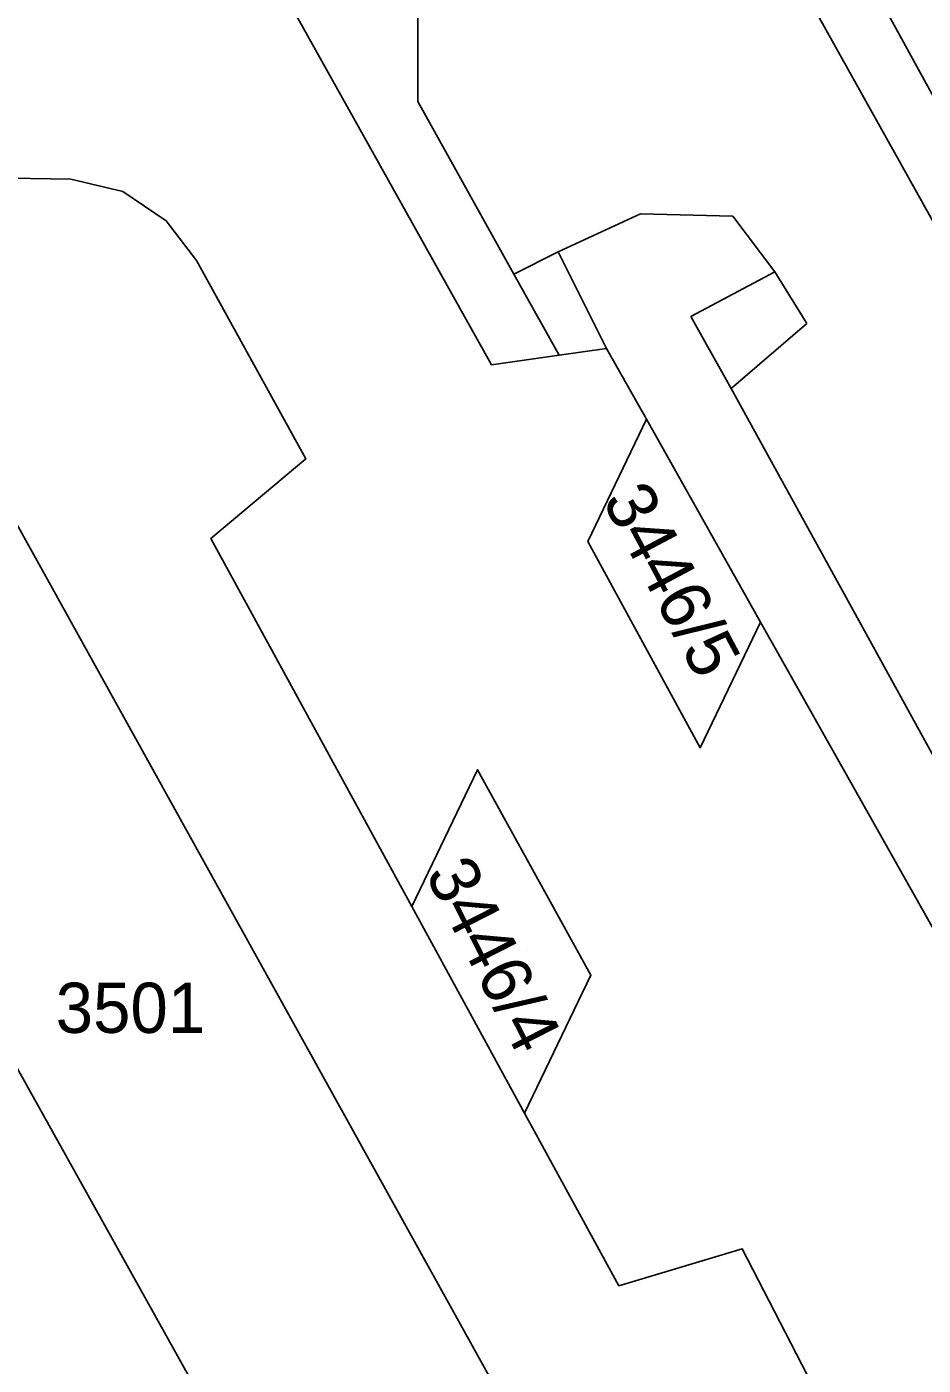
# Model space of a CAD drawing. Extents: x -262715 to -259381, y -1237238 to -1231182.
# Drawn here: x -261417 to -261381.4, y -1235699.9 to -1235646.6 of the extents above; entities that cross this region are included whole.
import ezdxf

# ---------------------------------------------------------------- set-up
doc = ezdxf.new("R2010")
doc.units = 0
for name, color, linetype in [('body_kn', 7, 'Continuous'), ('kladpar_druhypozemkov', 7, 'Continuous'), ('kladpar_hranice', 7, 'Continuous'), ('kladpar_parcelnecisla', 7, 'Continuous'), ('kladpar_plochy', 7, 'Continuous'), ('zappar_hrandruhpozemk', 7, 'Continuous')]:
    doc.layers.add(name, color=color, linetype=linetype)

msp = doc.modelspace()

# ---------------------------------------------------------------- linework, layer by layer
at = {"layer": 'body_kn'}
for p, q in [((-261401.47, -1235649.56), (-261401.47, -1235649.56)), ((-261415.28, -1235652.66), (-261415.28, -1235652.66)), ((-261413.21, -1235653.15), (-261413.21, -1235653.15)), ((-261392.61, -1235654.03), (-261392.61, -1235654.03)), ((-261388.94, -1235654.12), (-261388.94, -1235654.12)), ((-261411.48, -1235654.31), (-261411.48, -1235654.31)), ((-261410.28, -1235655.89), (-261410.28, -1235655.89)), ((-261395.88, -1235655.54), (-261395.88, -1235655.54)), ((-261395.88, -1235655.54), (-261395.88, -1235655.54)), ((-261387.26, -1235656.34), (-261387.26, -1235656.34)), ((-261397.65, -1235656.43), (-261397.65, -1235656.43)), ((-261397.65, -1235656.43), (-261397.65, -1235656.43)), ((-261390.6, -1235658.12), (-261390.6, -1235658.12)), ((-261385.99, -1235658.4), (-261385.99, -1235658.4)), ((-261393.96, -1235659.39), (-261393.96, -1235659.39)), ((-261398.54, -1235660.04), (-261398.54, -1235660.04)), ((-261395.85, -1235659.66), (-261395.85, -1235659.66)), ((-261389, -1235660.98), (-261389, -1235660.98)), ((-261389, -1235660.98), (-261389, -1235660.98)), ((-261392.37, -1235662.21), (-261392.37, -1235662.21)), ((-261392.37, -1235662.21), (-261392.37, -1235662.21)), ((-261405.93, -1235663.79), (-261405.93, -1235663.79)), ((-261405.93, -1235663.79), (-261405.93, -1235663.79)), ((-261409.71, -1235666.96), (-261409.71, -1235666.96)), ((-261394.71, -1235667.07), (-261394.71, -1235667.07)), ((-261387.83, -1235670.28), (-261387.83, -1235670.28)), ((-261387.83, -1235670.28), (-261387.83, -1235670.28)), ((-261390.23, -1235675.28), (-261390.23, -1235675.28)), ((-261399.09, -1235676.16), (-261399.09, -1235676.16)), ((-261401.71, -1235681.6), (-261401.71, -1235681.6)), ((-261401.71, -1235681.6), (-261401.71, -1235681.6)), ((-261394.58, -1235684.33), (-261394.58, -1235684.33)), ((-261397.22, -1235689.82), (-261397.22, -1235689.82)), ((-261397.22, -1235689.82), (-261397.22, -1235689.82)), ((-261388.56, -1235695.22), (-261388.56, -1235695.22)), ((-261393.47, -1235696.69), (-261393.47, -1235696.69))]:
    msp.add_line(p, q, dxfattribs=at)
at = {"layer": 'kladpar_druhypozemkov'}
for p, q in [((-261389.98, -1235668.92), (-261389.98, -1235668.92)), ((-261397.12, -1235683.38), (-261397.12, -1235683.38)), ((-261413.17, -1235684.66), (-261413.17, -1235684.66))]:
    msp.add_line(p, q, dxfattribs=at)
at = {"layer": 'kladpar_hranice'}
for p, q in [((-261392.37, -1235662.21), (-261387.83, -1235670.28)), ((-261397.22, -1235689.82), (-261401.71, -1235681.6))]:
    msp.add_line(p, q, dxfattribs=at)
for points in [[(-261589.5, -1235316.23), (-261558.55, -1235373.38), (-261545.48, -1235395.38), (-261529.32, -1235425.1), (-261511.21, -1235458.13), (-261492.65, -1235492.14), (-261486.88, -1235501.6), (-261475.01, -1235519.76), (-261455.64, -1235559.31), (-261446.9, -1235569.53), (-261445.58, -1235571), (-261434.14, -1235591.59), (-261432.99, -1235593.76), (-261426.79, -1235608.76), (-261415.88, -1235628.94), (-261409.46, -1235640.49), (-261398.54, -1235660.04), (-261395.85, -1235659.66), (-261393.96, -1235659.39), (-261392.37, -1235662.21)], [(-261401.71, -1235681.6), (-261409.71, -1235666.96), (-261405.93, -1235663.79), (-261410.28, -1235655.89), (-261411.48, -1235654.31), (-261413.21, -1235653.15), (-261415.28, -1235652.66), (-261418.53, -1235652.6), (-261420.69, -1235653.54), (-261424.38, -1235647.44), (-261421.97, -1235645.54), (-261420.75, -1235643.18), (-261420.2, -1235640.22), (-261420.71, -1235637.44), (-261425.09, -1235629.28), (-261435.51, -1235617.79), (-261446.22, -1235598.57), (-261448.98, -1235591.27), (-261453.34, -1235581.02), (-261459.9, -1235567.4), (-261464.77, -1235569.24), (-261486.46, -1235529.8), (-261505.16, -1235495.58)], [(-261390.22, -1235736.84), (-261437.66, -1235651.7), (-261461.76, -1235608.43), (-261467.86, -1235597.89), (-261523.57, -1235497.42)], [(-261352.7, -1235701.57), (-261356.45, -1235698.78), (-261375.96, -1235663.31), (-261392.09, -1235634.4), (-261401.48, -1235640.18), (-261403.28, -1235637.04), (-261396.15, -1235632.64), (-261395.33, -1235631.71), (-261395.49, -1235630.29), (-261406.15, -1235610.79), (-261420.15, -1235585.99), (-261421.33, -1235584.92), (-261422.94, -1235585.32), (-261434.14, -1235591.59), (-261445.58, -1235571), (-261446.9, -1235569.53), (-261442.73, -1235566.89), (-261441.26, -1235564.87), (-261441.82, -1235562.85), (-261455.34, -1235538.18), (-261469.51, -1235511.93), (-261466.57, -1235510.22)], [(-261368.01, -1235705.48), (-261387.83, -1235670.28), (-261392.37, -1235662.21), (-261393.96, -1235659.39), (-261395.85, -1235659.66), (-261398.54, -1235660.04), (-261409.46, -1235640.49), (-261415.88, -1235628.94), (-261426.79, -1235608.76), (-261432.99, -1235593.76), (-261434.14, -1235591.59), (-261422.94, -1235585.32), (-261421.33, -1235584.92), (-261420.15, -1235585.99), (-261406.15, -1235610.79), (-261395.49, -1235630.29), (-261395.33, -1235631.71), (-261396.15, -1235632.64), (-261403.28, -1235637.04)], [(-261407.7, -1235600.94), (-261403.03, -1235609.1), (-261401.85, -1235611.11), (-261394.91, -1235623.98), (-261393.78, -1235625.97), (-261388.88, -1235634.8), (-261387.77, -1235636.94), (-261380.64, -1235649.93), (-261379.45, -1235652.11), (-261375.1, -1235660.07), (-261373.94, -1235662.27), (-261366.9, -1235675.1), (-261365.77, -1235677.17), (-261354.62, -1235697.41), (-261352.48, -1235699.44), (-261349.4, -1235698.97), (-261332.6, -1235689.38)], [(-261332.6, -1235689.38), (-261349.4, -1235698.97), (-261352.48, -1235699.44), (-261354.62, -1235697.41), (-261365.77, -1235677.17), (-261366.9, -1235675.1), (-261373.94, -1235662.27), (-261375.1, -1235660.07), (-261379.45, -1235652.11), (-261380.64, -1235649.93), (-261387.77, -1235636.94), (-261388.88, -1235634.8), (-261393.78, -1235625.97), (-261394.91, -1235623.98), (-261401.85, -1235611.11), (-261403.03, -1235609.1), (-261407.7, -1235600.94)], [(-261452.54, -1235603.16), (-261442.43, -1235621.28), (-261431.37, -1235641.24), (-261434.67, -1235644.77), (-261433.26, -1235646.14), (-261431.36, -1235647.27), (-261429.38, -1235647.89), (-261427.07, -1235648.14), (-261424.38, -1235647.44), (-261420.69, -1235653.54), (-261422.8, -1235655.3), (-261424.28, -1235657.92), (-261424.54, -1235661.82), (-261423.27, -1235664.95), (-261418.92, -1235663.7), (-261397.54, -1235702.26)], [(-261488.56, -1235619.47), (-261468.61, -1235607.37), (-261467.06, -1235606.61), (-261465.15, -1235606.35), (-261463.23, -1235606.99), (-261461.76, -1235608.43), (-261437.66, -1235651.7), (-261390.22, -1235736.84)], [(-261365.39, -1235703.9), (-261389, -1235660.98), (-261390.6, -1235658.12), (-261387.26, -1235656.34), (-261388.94, -1235654.12), (-261392.61, -1235654.03), (-261395.88, -1235655.54), (-261397.65, -1235656.43), (-261401.47, -1235649.56), (-261401.48, -1235640.18), (-261392.09, -1235634.4), (-261375.96, -1235663.31), (-261356.45, -1235698.78), (-261352.7, -1235701.57)], [(-261403.28, -1235637.04), (-261401.48, -1235640.18), (-261401.47, -1235649.56), (-261397.65, -1235656.43), (-261395.88, -1235655.54), (-261392.61, -1235654.03), (-261388.94, -1235654.12), (-261387.26, -1235656.34), (-261390.6, -1235658.12), (-261389, -1235660.98), (-261365.39, -1235703.9)], [(-261397.54, -1235702.26), (-261418.92, -1235663.7), (-261423.27, -1235664.95), (-261424.54, -1235661.82), (-261424.28, -1235657.92), (-261422.8, -1235655.3), (-261420.69, -1235653.54), (-261418.53, -1235652.6), (-261415.28, -1235652.66), (-261413.21, -1235653.15), (-261411.48, -1235654.31), (-261410.28, -1235655.89), (-261405.93, -1235663.79)], [(-261387.83, -1235670.28), (-261390.23, -1235675.28), (-261394.71, -1235667.07), (-261392.37, -1235662.21)], [(-261392.37, -1235662.21), (-261394.71, -1235667.07), (-261390.23, -1235675.28), (-261387.83, -1235670.28)], [(-261405.93, -1235663.79), (-261409.71, -1235666.96), (-261401.71, -1235681.6), (-261397.22, -1235689.82), (-261393.47, -1235696.69), (-261388.56, -1235695.22), (-261371.33, -1235728.63)], [(-261387.83, -1235670.28), (-261368.01, -1235705.48), (-261371.99, -1235708.77), (-261371.04, -1235709.55), (-261365.53, -1235722.64), (-261364.25, -1235725.87), (-261359.1, -1235741.48), (-261352.38, -1235766.78), (-261351.19, -1235772.76), (-261348.93, -1235790.01), (-261350.64, -1235820.21), (-261351.68, -1235824.27), (-261355.45, -1235838.38), (-261358.1, -1235846.74), (-261360.53, -1235852.69), (-261362.88, -1235858.42), (-261365.45, -1235864.71), (-261367.16, -1235868.27)], [(-261401.71, -1235681.6), (-261399.09, -1235676.16), (-261394.58, -1235684.33), (-261397.22, -1235689.82)], [(-261397.22, -1235689.82), (-261394.58, -1235684.33), (-261399.09, -1235676.16), (-261401.71, -1235681.6)], [(-261384.6, -1235886.83), (-261372.3, -1235860.94), (-261365.4, -1235844.05), (-261361.59, -1235832.06), (-261360.62, -1235828.38), (-261358.61, -1235819.64), (-261356.53, -1235790.61), (-261358.05, -1235779.04), (-261358.59, -1235775.82), (-261362.93, -1235755.98), (-261365.55, -1235746.37), (-261371.33, -1235728.63), (-261388.56, -1235695.22), (-261393.47, -1235696.69), (-261397.22, -1235689.82)]]:
    msp.add_lwpolyline(points, dxfattribs=at)
at = {"layer": 'kladpar_plochy'}
for points in [[(-261589.5, -1235316.23), (-261558.55, -1235373.38), (-261545.48, -1235395.38), (-261529.32, -1235425.1), (-261511.21, -1235458.13), (-261492.65, -1235492.14), (-261486.88, -1235501.6), (-261475.01, -1235519.76), (-261455.64, -1235559.31), (-261446.9, -1235569.53), (-261445.58, -1235571), (-261434.14, -1235591.59), (-261432.99, -1235593.76), (-261426.79, -1235608.76), (-261415.88, -1235628.94), (-261409.46, -1235640.49), (-261398.54, -1235660.04), (-261395.85, -1235659.66), (-261393.96, -1235659.39), (-261392.37, -1235662.21), (-261394.71, -1235667.07), (-261390.23, -1235675.28), (-261387.83, -1235670.28), (-261368.01, -1235705.48)], [(-261390.22, -1235736.84), (-261437.66, -1235651.7), (-261461.76, -1235608.43), (-261467.86, -1235597.89), (-261523.57, -1235497.42)], [(-261352.7, -1235701.57), (-261356.45, -1235698.78), (-261375.96, -1235663.31), (-261392.09, -1235634.4), (-261401.48, -1235640.18), (-261403.28, -1235637.04), (-261396.15, -1235632.64), (-261395.33, -1235631.71), (-261395.49, -1235630.29), (-261406.15, -1235610.79), (-261420.15, -1235585.99), (-261421.33, -1235584.92), (-261422.94, -1235585.32), (-261434.14, -1235591.59), (-261445.58, -1235571), (-261446.9, -1235569.53), (-261442.73, -1235566.89), (-261441.26, -1235564.87), (-261441.82, -1235562.85), (-261455.34, -1235538.18), (-261469.51, -1235511.93)], [(-261420.15, -1235585.99), (-261406.15, -1235610.79), (-261395.49, -1235630.29), (-261395.33, -1235631.71), (-261396.15, -1235632.64), (-261403.28, -1235637.04), (-261401.48, -1235640.18), (-261401.47, -1235649.56), (-261397.65, -1235656.43), (-261395.88, -1235655.54), (-261392.61, -1235654.03), (-261388.94, -1235654.12), (-261387.26, -1235656.34), (-261390.6, -1235658.12), (-261389, -1235660.98), (-261365.39, -1235703.9)], [(-261368.01, -1235705.48), (-261387.83, -1235670.28), (-261392.37, -1235662.21), (-261393.96, -1235659.39), (-261395.85, -1235659.66), (-261398.54, -1235660.04), (-261409.46, -1235640.49), (-261415.88, -1235628.94), (-261426.79, -1235608.76), (-261432.99, -1235593.76)], [(-261371.33, -1235728.63), (-261388.56, -1235695.22), (-261393.47, -1235696.69), (-261397.22, -1235689.82), (-261394.58, -1235684.33), (-261399.09, -1235676.16), (-261401.71, -1235681.6), (-261409.71, -1235666.96), (-261405.93, -1235663.79), (-261410.28, -1235655.89), (-261411.48, -1235654.31), (-261413.21, -1235653.15), (-261415.28, -1235652.66), (-261418.53, -1235652.6), (-261420.69, -1235653.54), (-261424.38, -1235647.44), (-261421.97, -1235645.54), (-261420.75, -1235643.18), (-261420.2, -1235640.22), (-261420.71, -1235637.44), (-261425.09, -1235629.28), (-261435.51, -1235617.79), (-261446.22, -1235598.57)], [(-261407.7, -1235600.94), (-261403.03, -1235609.1), (-261401.85, -1235611.11), (-261394.91, -1235623.98), (-261393.78, -1235625.97), (-261388.88, -1235634.8), (-261387.77, -1235636.94), (-261380.64, -1235649.93), (-261379.45, -1235652.11), (-261375.1, -1235660.07), (-261373.94, -1235662.27), (-261366.9, -1235675.1), (-261365.77, -1235677.17), (-261354.62, -1235697.41), (-261352.48, -1235699.44), (-261349.4, -1235698.97), (-261332.6, -1235689.38)], [(-261332.6, -1235689.38), (-261349.4, -1235698.97), (-261352.48, -1235699.44), (-261354.62, -1235697.41), (-261365.77, -1235677.17), (-261366.9, -1235675.1), (-261373.94, -1235662.27), (-261375.1, -1235660.07), (-261379.45, -1235652.11), (-261380.64, -1235649.93), (-261387.77, -1235636.94), (-261388.88, -1235634.8), (-261393.78, -1235625.97), (-261394.91, -1235623.98), (-261401.85, -1235611.11), (-261403.03, -1235609.1), (-261407.7, -1235600.94)], [(-261452.54, -1235603.16), (-261442.43, -1235621.28), (-261431.37, -1235641.24), (-261434.67, -1235644.77), (-261433.26, -1235646.14), (-261431.36, -1235647.27), (-261429.38, -1235647.89), (-261427.07, -1235648.14), (-261424.38, -1235647.44), (-261420.69, -1235653.54), (-261422.8, -1235655.3), (-261424.28, -1235657.92), (-261424.54, -1235661.82), (-261423.27, -1235664.95), (-261418.92, -1235663.7), (-261397.54, -1235702.26)], [(-261365.39, -1235703.9), (-261389, -1235660.98), (-261390.6, -1235658.12), (-261387.26, -1235656.34), (-261388.94, -1235654.12), (-261392.61, -1235654.03), (-261395.88, -1235655.54), (-261397.65, -1235656.43), (-261401.47, -1235649.56), (-261401.48, -1235640.18), (-261392.09, -1235634.4), (-261375.96, -1235663.31), (-261356.45, -1235698.78), (-261352.7, -1235701.57)], [(-261437.66, -1235651.7), (-261390.22, -1235736.84)], [(-261397.54, -1235702.26), (-261418.92, -1235663.7), (-261423.27, -1235664.95), (-261424.54, -1235661.82), (-261424.28, -1235657.92), (-261422.8, -1235655.3), (-261420.69, -1235653.54), (-261418.53, -1235652.6), (-261415.28, -1235652.66), (-261413.21, -1235653.15), (-261411.48, -1235654.31), (-261410.28, -1235655.89), (-261405.93, -1235663.79), (-261409.71, -1235666.96), (-261401.71, -1235681.6), (-261397.22, -1235689.82), (-261393.47, -1235696.69), (-261388.56, -1235695.22), (-261371.33, -1235728.63)]]:
    msp.add_lwpolyline(points, dxfattribs=at)
for points in [[(-261392.37, -1235662.21), (-261387.83, -1235670.28), (-261390.23, -1235675.28), (-261394.71, -1235667.07)], [(-261397.22, -1235689.82), (-261401.71, -1235681.6), (-261399.09, -1235676.16), (-261394.58, -1235684.33)]]:
    msp.add_lwpolyline(points, close=True, dxfattribs=at)
at = {"layer": 'zappar_hrandruhpozemk'}
for p, q in [((-261395.88, -1235655.54), (-261393.96, -1235659.39)), ((-261385.99, -1235658.4), (-261387.26, -1235656.34)), ((-261397.65, -1235656.43), (-261395.85, -1235659.66)), ((-261389, -1235660.98), (-261385.99, -1235658.4))]:
    msp.add_line(p, q, dxfattribs=at)

# ---------------------------------------------------------------- texts
at = {"layer": 'kladpar_parcelnecisla'}
for s, rotation, p in [('3446/5', 298, (-261394.154, -1235665.438)), ('3446/4', 297, (-261401.199, -1235680.301))]:
    msp.add_text(s, height=2, rotation=rotation, dxfattribs=at).set_placement(p)
msp.add_text('3501', height=2, dxfattribs=at).set_placement((-261415.88, -1235686.63))

doc.saveas('drawing.dxf')
